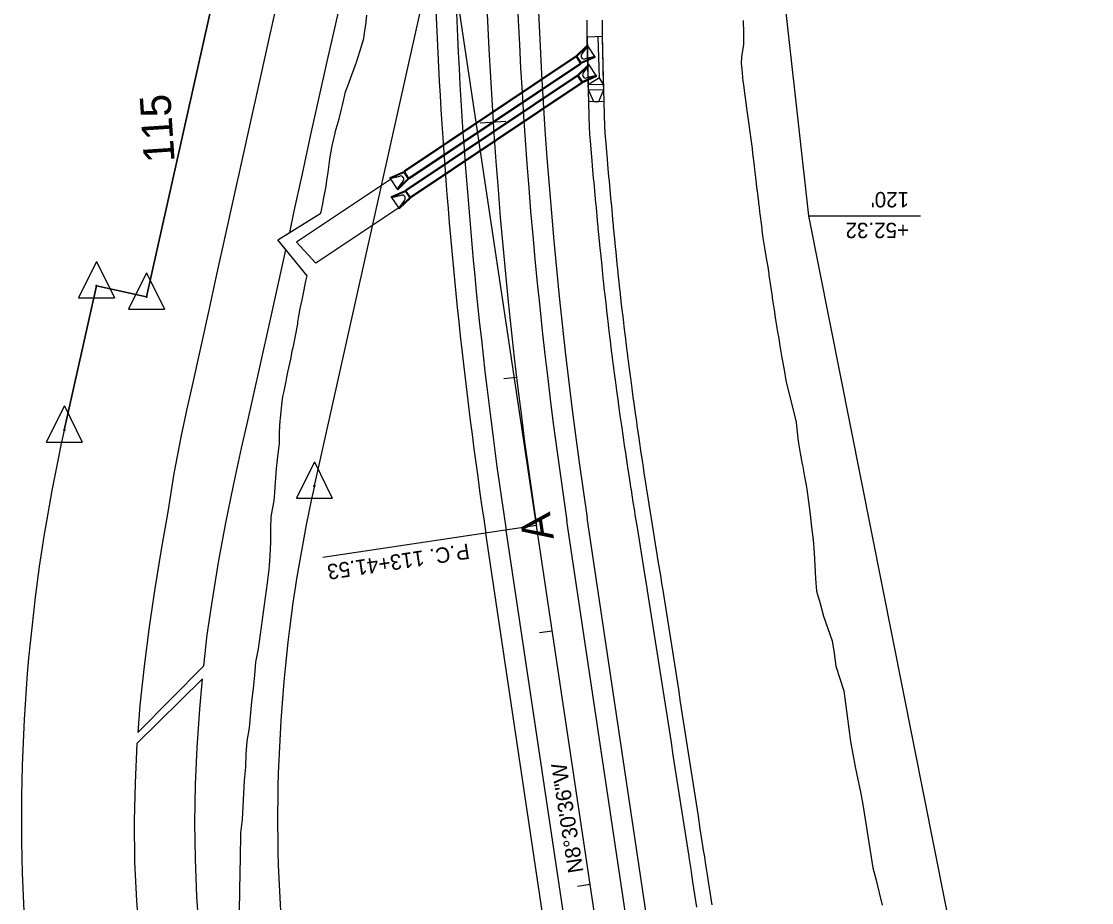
# Model space of a CAD drawing. Extents: x 609264 to 611265, y 427753 to 431566.
# Drawn here: x 610708.3 to 611125.9, y 429473.9 to 429817.8 of the extents above; entities that cross this region are included whole.
import ezdxf

# ---------------------------------------------------------------- set-up
doc = ezdxf.new("R2010")
doc.units = 0
for name, color, linetype in [('R_Drainage', 7, 'Continuous'), ('R_Horz Alg', 7, 'Continuous'), ('R_Horz Alg Annot', 7, 'Continuous'), ('R_Horz Alg Station', 7, 'Continuous'), ('R_Horz Alg Station Annot', 7, 'Continuous'), ('R_Horz Bearings', 7, 'Continuous'), ('R_Obliterate', 7, 'Continuous'), ('R_Proposed Const Limits', 7, 'Continuous'), ('R_Proposed Road', 7, 'Continuous'), ('R_Proposed Shoulder', 7, 'Continuous'), ('R_Restraining Conditions', 7, 'Continuous'), ('R_ROW', 7, 'Continuous'), ('R_ROW Annot', 7, 'Continuous'), ('S_EXIST_ROW', 7, 'Continuous')]:
    doc.layers.add(name, color=color, linetype=linetype)

msp = doc.modelspace()

# ---------------------------------------------------------------- linework, layer by layer
at = {"layer": 'R_Drainage'}
for p, q in [((610924.56, 429804.14), (610929.08, 429808.48)), ((610929.08, 429808.48), (610926.93, 429805.09)), ((610929.25, 429808.23), (610929.08, 429808.48)), ((610933.88, 429795.71), (610933.4, 429811.8)), ((610924.56, 429804.14), (610857.67, 429759.34)), ((610924.73, 429803.9), (610924.56, 429804.14)), ((610924.99, 429804.03), (610929.25, 429808.23)), ((610929.25, 429808.23), (610926.93, 429805.09)), ((610932.03, 429804.08), (610929.25, 429808.23)), ((610924.73, 429803.9), (610857.83, 429759.09)), ((610926.41, 429801.39), (610859.51, 429756.58)), ((610926.57, 429801.15), (610859.68, 429756.34)), ((610924.97, 429804.06), (610924.73, 429803.9)), ((610924.73, 429803.9), (610926.31, 429801.54)), ((610924.97, 429804.06), (610926.55, 429801.7)), ((610925.15, 429796.71), (610929.67, 429801.04)), ((610925.57, 429796.6), (610929.83, 429800.8)), ((610926.55, 429801.7), (610926.31, 429801.54)), ((610926.31, 429801.54), (610926.47, 429801.3)), ((610926.47, 429801.3), (610932.2, 429803.83)), ((610926.53, 429801.73), (610932.03, 429804.08)), ((610929.67, 429801.04), (610927.52, 429797.65)), ((610929.83, 429800.8), (610927.52, 429797.65)), ((610932.03, 429804.08), (610928.24, 429803.13)), ((610932.2, 429803.83), (610928.24, 429803.13)), ((610929.83, 429800.8), (610929.67, 429801.04)), ((610932.61, 429796.64), (610929.83, 429800.8)), ((610932.03, 429804.08), (610932.2, 429803.83)), ((610925.15, 429796.71), (610858.25, 429751.9)), ((610925.31, 429796.47), (610858.41, 429751.66)), ((610925.31, 429796.47), (610925.15, 429796.71)), ((610925.55, 429796.63), (610925.31, 429796.47)), ((610925.31, 429796.47), (610926.89, 429794.11)), ((610925.55, 429796.63), (610927.13, 429794.27)), ((610927.05, 429793.86), (610932.78, 429796.4)), ((610927.11, 429794.3), (610932.61, 429796.64)), ((610932.61, 429796.64), (610928.82, 429795.7)), ((610932.78, 429796.4), (610928.82, 429795.7)), ((610932.61, 429796.64), (610932.78, 429796.4)), ((610926.99, 429793.96), (610860.1, 429749.15)), ((610927.15, 429793.72), (610860.26, 429748.91)), ((610927.13, 429794.27), (610926.89, 429794.11)), ((610926.89, 429794.11), (610927.05, 429793.86)), ((610935.45, 429793.2), (610929.46, 429793.05)), ((610929.51, 429791.04), (610929.46, 429793.05)), ((610935.51, 429791.19), (610935.45, 429793.2)), ((610929.51, 429791.04), (610935.51, 429791.19)), ((610935.62, 429786.52), (610929.63, 429786.37)), ((610857.73, 429759.25), (610852, 429756.72)), ((610857.67, 429758.82), (610852.17, 429756.47)), ((610857.65, 429758.85), (610857.89, 429759.01)), ((610859.23, 429756.49), (610857.65, 429758.85)), ((610857.89, 429759.01), (610857.73, 429759.25)), ((610859.47, 429756.65), (610857.89, 429759.01)), ((610852.36, 429756.14), (610815.59, 429731.66)), ((610852, 429756.72), (610855.95, 429757.42)), ((610852.17, 429756.47), (610852, 429756.72)), ((610852.17, 429756.47), (610855.95, 429757.42)), ((610852.17, 429756.47), (610854.95, 429752.32)), ((610859.21, 429756.52), (610854.95, 429752.32)), ((610854.95, 429752.32), (610857.26, 429755.47)), ((610859.63, 429756.41), (610855.11, 429752.07)), ((610855.11, 429752.07), (610857.26, 429755.47)), ((610859.23, 429756.49), (610859.47, 429756.65)), ((610859.47, 429756.65), (610859.63, 429756.41)), ((610858.31, 429751.82), (610852.58, 429749.29)), ((610852.58, 429749.29), (610856.54, 429749.99)), ((610858.25, 429751.38), (610852.75, 429749.04)), ((610852.75, 429749.04), (610856.54, 429749.99)), ((610854.95, 429752.32), (610855.11, 429752.07)), ((610858.23, 429751.41), (610858.47, 429751.58)), ((610859.81, 429749.05), (610858.23, 429751.41)), ((610858.47, 429751.58), (610858.31, 429751.82)), ((610860.05, 429749.21), (610858.47, 429751.58)), ((610852.75, 429749.04), (610852.58, 429749.29)), ((610852.75, 429749.04), (610855.53, 429744.89)), ((610859.79, 429749.08), (610855.53, 429744.89)), ((610855.53, 429744.89), (610857.84, 429748.03)), ((610860.22, 429748.97), (610855.69, 429744.64)), ((610855.69, 429744.64), (610857.84, 429748.03)), ((610859.81, 429749.05), (610860.05, 429749.21)), ((610860.05, 429749.21), (610860.22, 429748.97)), ((610855.51, 429745.02), (610823.11, 429723.45)), ((610855.53, 429744.89), (610855.69, 429744.64)), ((610815.59, 429731.66), (610823.11, 429723.45))]:
    msp.add_line(p, q, dxfattribs=at)
for points in [[(610971.88, 429472.12), (610971.11, 429477.07), (610970.35, 429482.01), (610970.07, 429483.82), (610969.58, 429486.95), (610968.85, 429491.66), (610968.81, 429491.89), (610968.05, 429496.83), (610967.28, 429501.77), (610966.51, 429506.71), (610965.74, 429511.65), (610964.98, 429516.59), (610964.21, 429521.53), (610963.44, 429526.47), (610962.68, 429531.42), (610961.91, 429536.36), (610961.14, 429541.3), (610960.37, 429546.24), (610959.61, 429551.18), (610958.84, 429556.12), (610958.07, 429561.06), (610957.31, 429566), (610956.54, 429570.94), (610956.53, 429571.01), (610955.77, 429575.88), (610955, 429580.81), (610954.2, 429585.74), (610953.41, 429590.68), (610952.61, 429595.62), (610952.45, 429596.64), (610952.43, 429596.77), (610951.82, 429600.55), (610951.03, 429605.49), (610950.23, 429610.43), (610949.44, 429615.36), (610948.64, 429620.3), (610947.85, 429625.24), (610947.61, 429626.75), (610947.07, 429630.11), (610946.31, 429634.94), (610946.26, 429635.25), (610945.55, 429639.78), (610944.95, 429643.76), (610944.82, 429644.63), (610944.09, 429649.47), (610943.68, 429652.28), (610943.38, 429654.32), (610942.68, 429659.17), (610942.44, 429660.8), (610941.99, 429664.02), (610941.31, 429668.87), (610941.25, 429669.33), (610940.65, 429673.73), (610940.1, 429677.86), (610940, 429678.59), (610939.36, 429683.44), (610938.98, 429686.41), (610938.8, 429687.83), (610938.74, 429688.31), (610938.3, 429691.8), (610938.13, 429693.17), (610937.9, 429694.95), (610937.53, 429698.03), (610937.35, 429699.53), (610936.96, 429702.92), (610936.89, 429703.52), (610936.41, 429707.79), (610935.94, 429712.08), (610935.88, 429712.66), (610935.57, 429715.5), (610935.36, 429717.53), (610935.03, 429720.65), (610934.85, 429722.41), (610934.35, 429727.28), (610934.16, 429729.22), (610933.87, 429732.16), (610933.4, 429737.03), (610933.32, 429737.79), (610933.14, 429739.76), (610933.07, 429740.5), (610933, 429741.2), (610932.93, 429741.91), (610932.64, 429745.01), (610932.52, 429746.36), (610932.48, 429746.79), (610932.03, 429751.67), (610931.73, 429754.94), (610931.59, 429756.55), (610931.16, 429761.43), (610930.98, 429763.52), (610930.73, 429766.31), (610930.32, 429771.19), (610930.24, 429772.1), (610929.9, 429776.24), (610929.13, 429805.45), (610929.12, 429806.72), (610929.09, 429810.56), (610929.06, 429815.33), (610929.06, 429815.46), (610929.05, 429818.27)], [(610977.81, 429473.05), (610977.04, 429477.99), (610976.28, 429482.93), (610976, 429484.74), (610975.51, 429487.87), (610974.78, 429492.58), (610974.74, 429492.81), (610973.97, 429497.75), (610973.21, 429502.69), (610972.44, 429507.63), (610971.67, 429512.57), (610970.91, 429517.51), (610970.14, 429522.45), (610969.37, 429527.39), (610968.61, 429532.34), (610967.84, 429537.28), (610967.07, 429542.22), (610966.3, 429547.16), (610965.54, 429552.1), (610964.77, 429557.04), (610964, 429561.98), (610963.24, 429566.92), (610962.47, 429571.86), (610962.46, 429571.93), (610961.7, 429576.81), (610960.92, 429581.75), (610960.13, 429586.7), (610959.33, 429591.63), (610958.54, 429596.57), (610958.37, 429597.59), (610958.35, 429597.73), (610957.74, 429601.51), (610956.95, 429606.44), (610956.16, 429611.38), (610955.36, 429616.32), (610954.57, 429621.25), (610953.77, 429626.19), (610953.53, 429627.7), (610953, 429631.05), (610952.23, 429635.87), (610952.19, 429636.17), (610951.48, 429640.7), (610950.88, 429644.66), (610950.75, 429645.52), (610950.02, 429650.36), (610949.61, 429653.15), (610949.31, 429655.19), (610948.61, 429660.02), (610948.38, 429661.64), (610947.93, 429664.86), (610947.26, 429669.7), (610947.19, 429670.15), (610946.6, 429674.53), (610946.04, 429678.66), (610945.95, 429679.37), (610945.31, 429684.22), (610944.93, 429687.17), (610944.75, 429688.59), (610944.69, 429689.06), (610944.25, 429692.55), (610944.08, 429693.91), (610943.86, 429695.69), (610943.48, 429698.76), (610943.3, 429700.23), (610942.92, 429703.6), (610942.85, 429704.2), (610942.37, 429708.45), (610941.9, 429712.73), (610941.84, 429713.3), (610941.54, 429716.14), (610941.32, 429718.16), (610941, 429721.27), (610940.82, 429723.02), (610940.32, 429727.88), (610940.13, 429729.81), (610939.84, 429732.74), (610939.37, 429737.61), (610939.3, 429738.36), (610939.11, 429740.33), (610939.04, 429741.07), (610938.97, 429741.76), (610938.91, 429742.48), (610938.62, 429745.57), (610938.49, 429746.92), (610938.45, 429747.34), (610938, 429752.21), (610937.71, 429755.48), (610937.57, 429757.08), (610937.13, 429761.95), (610936.95, 429764.04), (610936.71, 429766.82), (610936.3, 429771.7), (610936.22, 429772.6), (610935.89, 429776.57), (610935.13, 429805.55), (610935.12, 429806.77), (610935.09, 429810.6), (610935.06, 429815.37), (610935.06, 429815.49), (610935.05, 429818.3)], [(610935.45, 429793.2), (610935.12, 429807.13), (610935.08, 429811.87), (610929.08, 429811.63), (610929.12, 429806.72), (610929.46, 429793.05)], [(610935.46, 429793.2), (610933.88, 429795.71), (610933.88, 429795.71), (610929.46, 429793.05)], [(610932.63, 429786.45), (610931.62, 429786.42), (610929.51, 429791.04)], [(610932.63, 429786.45), (610933.63, 429786.47), (610935.51, 429791.19)]]:
    msp.add_lwpolyline(points, dxfattribs=at)
for centre, start, end in [((610927.94, 429804.34), 143.6349, 283.9963), ((610928.52, 429796.91), 143.6349, 283.9963), ((610856.26, 429756.21), 323.6349, 103.9963), ((610856.84, 429748.77), 323.6349, 103.9963)]:
    msp.add_arc(centre, 1.25, start, end, dxfattribs=at)
at = {"layer": 'R_Horz Alg'}
msp.add_line((611107.78, 428294.28), (610909.26, 429621.04), dxfattribs=at)
msp.add_arc((612798.1, 429903.66), 1909.86, 167.41778, 188.50997, dxfattribs=at)
at = {"layer": 'R_Horz Alg Annot'}
msp.add_line((610909.26, 429621.04), (610856.65, 429972.69), dxfattribs=at)
at = {"layer": 'R_Horz Alg Station'}
for points in [[(610887.35, 429778.23), (610897.33, 429778.89)], [(610896.53, 429678.41), (610901.5, 429678.99)], [(610909.26, 429621.04), (610825.89, 429608.56)], [(610910.46, 429579.23), (610915.41, 429579.97)], [(610925.26, 429480.33), (610930.21, 429481.07)]]:
    msp.add_lwpolyline(points, dxfattribs=at)
at = {"layer": 'R_Obliterate'}
for p, q in [((610753.64, 429540.31), (610779.52, 429566.34)), ((610779, 429561.16), (610753.32, 429536.01)), ((610753.32, 429536.01), (610752.6, 429520.59))]:
    msp.add_line(p, q, dxfattribs=at)
for points in [[(610812.96, 429735.41), (610814.75, 429743.71), (610817.91, 429758.35), (610821.1, 429772.98), (610824.35, 429787.61), (610827.65, 429802.18), (610830.94, 429816.8), (610834.24, 429831.41), (610837.58, 429846.02), (610840.87, 429860.64), (610844.1, 429874.92)], [(610817.21, 429865.94), (610813.98, 429851.31), (610810.7, 429836.68), (610807.36, 429822.08), (610804.03, 429807.47), (610800.76, 429792.81), (610797.52, 429778.17), (610794.28, 429763.55), (610791.03, 429748.91), (610787.8, 429734.28), (610784.54, 429719.65), (610781.35, 429705.03), (610778.18, 429690.38), (610774.95, 429675.75), (610772.86, 429666.54), (610770.67, 429656.14), (610767.8, 429641.34), (610765.35, 429626.4), (610762.85, 429611.63), (610760.33, 429596.4), (610758.08, 429581.46), (610756.13, 429566.21), (610754.43, 429550.93), (610753.64, 429540.31)], [(610811.5, 429728.63), (610808.3, 429732.51), (610812.96, 429735.41)], [(610779.52, 429566.34), (610780.82, 429578.37), (610782.58, 429590.4), (610785.05, 429605.87), (610785.3, 429607.39), (610788, 429622.13), (610791, 429636.68), (610794.19, 429651.22), (610796.65, 429661.96), (610798.59, 429670.56), (610801.84, 429685.19), (610805.1, 429699.81), (610808.35, 429714.45), (610811.5, 429728.63)], [(610780.44, 429438.59), (610779.25, 429447.05), (610777.75, 429461.34), (610776.75, 429476.28), (610776.18, 429490.93), (610775.96, 429505.05), (610776.14, 429520.02), (610776.84, 429534.46), (610777.93, 429549.4), (610779, 429561.16)], [(610752.6, 429520.59), (610752.23, 429505.61), (610752.46, 429489.81), (610753.17, 429474.53), (610754.29, 429459.61), (610755.88, 429444.15), (610757.08, 429435.37)]]:
    msp.add_lwpolyline(points, dxfattribs=at)
at = {"layer": 'R_Proposed Const Limits'}
for points in [[(610804.25, 429598.73), (610805.01, 429603.9), (610805.1, 429605.45), (610805.3, 429609.19), (610805.54, 429614.55), (610805.55, 429614.89), (610805.61, 429619.89), (610805.71, 429624.27), (610805.9, 429625.25), (610806.95, 429630.71), (610807.18, 429633.81), (610807.34, 429636.07), (610807.72, 429641.42), (610807.84, 429643.22), (610808.21, 429646.79), (610808.9, 429652.17), (610808.97, 429652.67), (610808.93, 429657.46), (610809.23, 429662), (610809.32, 429662.79), (610809.9, 429668.14), (610810.35, 429671.41), (610810.66, 429672.99), (610810.77, 429673.52), (610811.54, 429677.4), (610811.84, 429678.91), (610812.24, 429680.89), (610812.99, 429684.3), (610813.35, 429685.95), (610814.12, 429689.69), (610814.26, 429690.35), (610815.24, 429695.06), (610816.09, 429699.77), (610816.19, 429700.4), (610816.72, 429703.52), (610817.09, 429705.73), (610817.78, 429709.15), (610818.18, 429711.08), (610819.32, 429716.42), (610819.8, 429718.54), (610808.3, 429732.51), (610825.14, 429742.99), (610825.85, 429746.53), (610826.19, 429748.27), (610827.15, 429753.54), (610827.5, 429755.79), (610827.98, 429758.79), (610828.68, 429764.02), (610828.8, 429764.99), (610829.56, 429769.26), (610830.67, 429774.22), (610830.75, 429774.52), (610832.29, 429779.79), (610833.19, 429783.47), (610833.56, 429785.03), (610834.77, 429790.26), (610835.64, 429792.68), (610836.67, 429795.52), (610838.61, 429800.78), (610838.99, 429801.91), (610840.34, 429806), (610841.87, 429811.08), (610841.9, 429811.22), (610842.34, 429814.18), (610842.62, 429816.38), (610843.1, 429820.16)], [(610989.9, 429818.09), (610990.06, 429813.47), (610990.05, 429811.07), (610990.04, 429809.75), (610990.03, 429808.73), (610989.33, 429803.94), (610989.15, 429801.36), (610989.41, 429799.19), (610989.78, 429794.46), (610990.04, 429793.06), (610990.44, 429789.75), (610991.12, 429785.05), (610991.16, 429784.78), (610991.73, 429780.34), (610992.27, 429776.68), (610992.3, 429776.51), (610992.43, 429775.63), (610993.09, 429770.93), (610993.39, 429768.24), (610993.63, 429766.22), (610994.17, 429761.51), (610994.35, 429759.96), (610994.73, 429756.8), (610995.29, 429752.1), (610995.34, 429751.69), (610995.5, 429750.38), (610995.87, 429747.39), (610995.95, 429746.7), (610996.04, 429746.03), (610996.13, 429745.32), (610996.36, 429743.42), (610996.45, 429742.69), (610997.05, 429737.99), (610997.41, 429735.16), (610997.66, 429733.29), (610998.38, 429728.6), (610998.68, 429726.92), (610999.21, 429723.93), (610999.54, 429721.98), (610999.92, 429719.24), (611000, 429718.69), (611000.59, 429714.56), (611001.19, 429710.45), (611001.27, 429709.87), (611001.76, 429706.62), (611001.98, 429705.19), (611002.45, 429702.23), (611002.73, 429700.51), (611003.49, 429695.84), (611003.56, 429695.38), (611003.79, 429694.01), (611004.29, 429691.17), (611005.08, 429686.5), (611005.2, 429685.81), (611005.88, 429681.84), (611006.62, 429677.61), (611006.7, 429677.18), (611010.62, 429661.38), (611010.87, 429658.66), (611011.39, 429653.97), (611011.53, 429653.13), (611012.21, 429649.31), (611012.98, 429644.95), (611013.04, 429644.66), (611013.88, 429640.01), (611014.48, 429636.78), (611014.76, 429635.28), (611015.44, 429630.33), (611016.05, 429625.36), (611016.66, 429620.4), (611017.27, 429615.44), (611017.62, 429610.43), (611017.92, 429605.42), (611018.22, 429600.41), (611018.57, 429595.41), (611020.01, 429590.57), (611020.54, 429588.63), (611021.34, 429585.71), (611022.99, 429580.9), (611024.62, 429576.09), (611025.47, 429571.16), (611026.13, 429566.2), (611027.61, 429561.37), (611029.22, 429556.56), (611029.92, 429551.61), (611030.56, 429546.64), (611031.2, 429541.68), (611031.83, 429536.72), (611032.71, 429531.8), (611033.7, 429526.89), (611034.68, 429521.98), (611035.69, 429517.08), (611036.63, 429512.16), (611037.36, 429507.22), (611038.16, 429502.28), (611038.97, 429497.35), (611039.78, 429492.41), (611040.59, 429487.48), (611041.78, 429482.6), (611042.98, 429477.72), (611044.18, 429472.85)], [(610780.44, 429438.59), (610793.86, 429440.45), (610793.8, 429445.49), (610793.84, 429450.56), (610793.46, 429465.43), (610793.45, 429465.67), (610793.43, 429470.72), (610793.61, 429485.91), (610793.78, 429490.99), (610793.9, 429501.12), (610794.52, 429506.27), (610794.82, 429511.37), (610795.03, 429516.46), (610795.33, 429521.56), (610795.79, 429526.68), (610796.02, 429531.77), (610796.36, 429536.88), (610797.31, 429542.08), (610798.22, 429552.33), (610798.86, 429557.48), (610799.3, 429562.6), (610799.71, 429567.72), (610800.73, 429572.92), (610804.25, 429598.73)]]:
    msp.add_lwpolyline(points, dxfattribs=at)
at = {"layer": 'R_Proposed Road'}
for p, q in [((611100.64, 428423.11), (610921.13, 429622.82)), ((611041.57, 428655.73), (610897.4, 429619.26))]:
    msp.add_line(p, q, dxfattribs=at)
for radius, start in [(1897.86, 170.45369), (1921.86, 176.59591)]:
    msp.add_arc((612798.1, 429903.66), radius, start, 188.50997, dxfattribs=at)
at = {"layer": 'R_Proposed Shoulder'}
for p, q in [((611112.77, 428396.14), (610929.04, 429624)), ((611025.84, 428706.82), (610889.48, 429618.08))]:
    msp.add_line(p, q, dxfattribs=at)
for radius, start in [(1889.86, 167.41778), (1929.86, 177.97809)]:
    msp.add_arc((612798.1, 429903.66), radius, start, 188.50997, dxfattribs=at)
at = {"layer": 'R_Restraining Conditions'}
for p, q in [((610824.41, 430011.86), (610757.09, 429710.26)), ((610737.57, 429714.61), (610724.99, 429658.27))]:
    msp.add_line(p, q, dxfattribs=at)
msp.add_lwpolyline([(610757.09, 429710.26), (610737.57, 429714.61)], dxfattribs=at)
msp.add_arc((611404.88, 429506.52), 696.62, 167.41778, 198.98444, dxfattribs=at)
at = {"layer": 'R_ROW'}
for points in [[(611015.56, 429741.88), (610995.63, 429920.47), (610990.88, 429963.12), (610986.42, 430003.18), (610982.55, 430037.76), (610977.26, 430085.17), (610983.75, 430219.78), (610992.27, 430396.71), (610992.27, 430396.71)], [(611107.97, 428799.88), (611125.91, 429186.79), (611015.56, 429741.88)]]:
    msp.add_lwpolyline(points, dxfattribs=at)
at = {"layer": 'R_ROW Annot'}
msp.add_line((611015.56, 429741.88), (611059.14, 429741.88), dxfattribs=at)
at = {"layer": 'S_EXIST_ROW'}
for p, q in [((610757.09, 429710.26), (610942.43, 430540.66)), ((610822.59, 429636.49), (611020.51, 430523.23)), ((610737.59, 429724.07), (610730.54, 429709.89)), ((610737.59, 429724.07), (610744.57, 429709.89)), ((610757.11, 429719.71), (610750.06, 429705.53)), ((610757.11, 429719.71), (610764.09, 429705.53)), ((610724.99, 429658.27), (610737.57, 429714.61)), ((610737.57, 429714.61), (610737.57, 429714.61)), ((610730.54, 429709.89), (610744.57, 429709.89)), ((610757.09, 429710.26), (610757.09, 429710.26)), ((610750.06, 429705.53), (610764.09, 429705.53)), ((610725.02, 429667.73), (610717.97, 429653.54)), ((610725.02, 429667.73), (610731.99, 429653.54)), ((610724.99, 429658.27), (610724.99, 429658.27)), ((610717.97, 429653.54), (610731.99, 429653.54)), ((610822.62, 429645.94), (610815.56, 429631.76)), ((610822.62, 429645.94), (610829.59, 429631.76)), ((610822.59, 429636.49), (610822.59, 429636.49)), ((610815.56, 429631.76), (610829.59, 429631.76))]:
    msp.add_line(p, q, dxfattribs=at)
msp.add_lwpolyline([(610737.57, 429714.61), (610757.09, 429710.26)], dxfattribs=at)
for centre, radius in [((610737.57, 429714.61), 0.24), ((610737.57, 429714.61), 0.12), ((610757.09, 429710.26), 0.24), ((610757.09, 429710.26), 0.12), ((610724.99, 429658.27), 0.24), ((610724.99, 429658.27), 0.12), ((610822.59, 429636.49), 0.24), ((610822.59, 429636.49), 0.12)]:
    msp.add_circle(centre, radius, dxfattribs=at)
for radius in [696.62, 596.62]:
    msp.add_arc((611404.88, 429506.52), radius, 167.41778, 198.98444, dxfattribs=at)

# ---------------------------------------------------------------- texts
at = {"layer": 'R_Horz Alg'}
msp.add_text('A', height=12, rotation=98.51, dxfattribs=at).set_placement((610916.09, 429615.99))
msp.add_text('A', height=12, rotation=98.51, dxfattribs=at).set_placement((610916.09, 429615.99))
msp.add_text('A', height=12, rotation=98.51, dxfattribs=at).set_placement((610916.09, 429615.99))
at = {"layer": 'R_Horz Alg Station Annot'}
for s, height, rotation, p in [('115', 12, 93.7558, (610768.09, 429763.02)), ('P.C. 113+41.53', 6, 188.51, (610882.66, 429614.06))]:
    msp.add_text(s, height=height, rotation=rotation, dxfattribs=at).set_placement(p)
at = {"layer": 'R_Horz Bearings'}
msp.add_text('N8%%d30\'36"W', height=6, rotation=99.0104, dxfattribs=at).set_placement((610927.64, 429485.93))
at = {"layer": 'R_ROW Annot'}
for s, p in [("120'", (611054.66, 429751.2)), ('+52.32', (611054.66, 429739.2))]:
    msp.add_text(s, height=6, rotation=180, dxfattribs=at).set_placement(p)

doc.saveas('drawing.dxf')
